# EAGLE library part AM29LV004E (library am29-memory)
4-Megabit FLASH MEMORY (512 K x 8 bit) CMOS 3 V-only boot sector flash memory
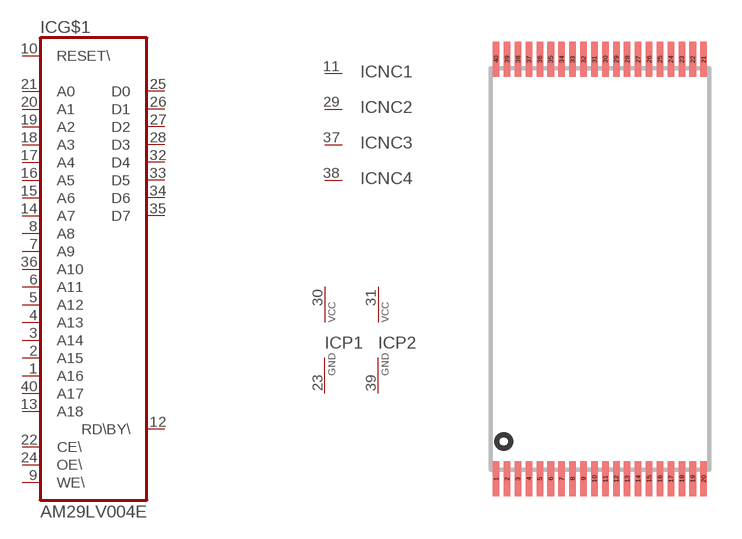
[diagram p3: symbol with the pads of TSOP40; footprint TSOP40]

Designator prefix IC; gates G$1=29LV004 NC1=NC P1=VCC-GND P2=VCC-GND NC2=NC NC3=NC NC4=NC

## AM29LV004E  [TSOP40]
1  G$1:A16  in
2  G$1:A15  in
3  G$1:A14  in
4  G$1:A13  in
5  G$1:A12  in
6  G$1:A11  in
7  G$1:A9  in
8  G$1:A8  in
9  G$1:WE\  in
10  G$1:RESET\  in
11  NC1:NC  nc
12  G$1:RD\BY\  out
13  G$1:A18  in
14  G$1:A7  in
15  G$1:A6  in
16  G$1:A5  in
17  G$1:A4  in
18  G$1:A3  in
19  G$1:A2  in
20  G$1:A1  in
21  G$1:A0  in
22  G$1:CE\  in
23  P1:GND  pwr
24  G$1:OE\  in
25  G$1:D0  hiz
26  G$1:D1  hiz
27  G$1:D2  hiz
28  G$1:D3  hiz
29  NC2:NC  nc
30  P1:VCC  pwr
31  P2:VCC  pwr
32  G$1:D4  hiz
33  G$1:D5  hiz
34  G$1:D6  hiz
35  G$1:D7  hiz
36  G$1:A10  in
37  NC3:NC  nc
38  NC4:NC  nc
39  P2:GND  pwr
40  G$1:A17  in

## Footprint TSOP40 (pad centres in mm)
Thin Small Outline Plastic Package
smd 0.3 x 1.6: 1 -4.75,-9.6; 2 -4.25,-9.6; 3 -3.75,-9.6; 4 -3.25,-9.6; 5 -2.75,-9.6; 6 -2.25,-9.6; 7 -1.75,-9.6; 8 -1.25,-9.6; 9 -0.75,-9.6; 10 -0.25,-9.6; 11 0.25,-9.6; 12 0.75,-9.6; 13 1.25,-9.6; 14 1.75,-9.6; 15 2.25,-9.6; 16 2.75,-9.6; 17 3.25,-9.6; 18 3.75,-9.6; 19 4.25,-9.6; 20 4.75,-9.6; 21 4.75,9.6; 22 4.25,9.6; 23 3.75,9.6; 24 3.25,9.6; 25 2.75,9.6; 26 2.25,9.6; 27 1.75,9.6; 28 1.25,9.6; 29 0.75,9.6; 30 0.25,9.6; 31 -0.25,9.6; 32 -0.75,9.6; 33 -1.25,9.6; 34 -1.75,9.6; 35 -2.25,9.6; 36 -2.75,9.6; 37 -3.25,9.6; 38 -3.75,9.6; 39 -4.25,9.6; 40 -4.75,9.6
